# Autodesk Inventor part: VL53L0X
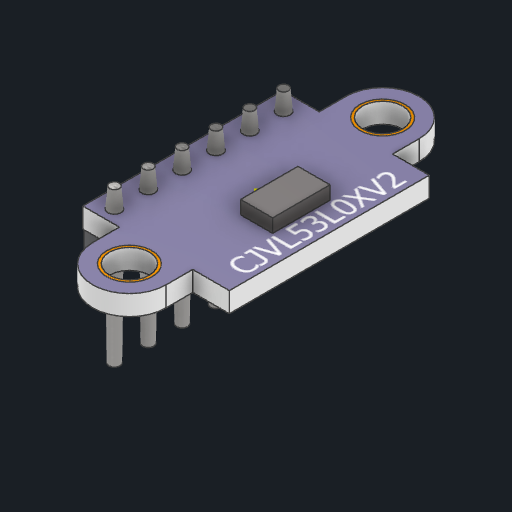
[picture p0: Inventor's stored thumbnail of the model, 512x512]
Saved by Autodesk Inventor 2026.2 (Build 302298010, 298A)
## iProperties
Created: 2026-04
Part Number: VL53L0X
Material: PPS 플라스틱
Document SubType Name: Modeling
Designer: work
Density: 1.637 g/cm^3
Appearance: 매끄러움 - 흰색
Author: work
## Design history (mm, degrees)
sketch "스케치1"
  geometry: L1 (-5.5, 7.5)-(5.5, 7.5); L2 (5.5, 7.5)-(5.5, -7.5); L3 (5.5, -7.5)-(-5.5, -7.5); L4 (-5.5, -7.5)-(-5.5, 7.5); L5 (-5.5, 7.5)-(5.5, -7.5); L6 (5.5, 7.5)-(-5.5, -7.5); L7 (0, 9.5)-(0, -9.5); L8 (0, 9.5)-(0, -9.5); L9 (-2.75, 9.5)-(-2.75, -9.5); L10 (2.75, -9.5)-(2.75, 9.5); C1 r 1.5 at (0, 9.5); C2 r 1.5 at (0, -9.5); A1 r 2.75 centre (0, 9.5) between (2.75, 9.5) and (-2.75, 9.5); A2 r 2.75 centre (0, -9.5) between (-2.75, -9.5) and (2.75, -9.5); 6 further points
  constraints: 22 end point, 6 midpoint, 4 centre point, 4 equal length, 4 point on circle, 4 tangent, 2 coincident, 1 horizontal, 1 perpendicular, 1 vertical
  dimensions: "d0" = 11 distance of L2.end L3.end; "d1" = 15 distance of L1.end L2.end; "d2" = 19 distance of L7.start L7.end; "d3" = 5.5 diameter of A2; "d4" = 3 diameter of C1; "d5" = 3 diameter of C2
extrude "돌출1" new body sketch "스케치1" distance "d6" = 1.5; taper "d7" = 0 deg
sketch "스케치2"
  geometry: L1 (5.5, -7.5)-(5.5, 7.5) reference; L2 (5.5, 0)-(-5.5, 0); L3 (-5.5, 7.5)-(-5.5, -7.5) reference; L4 (3.4, -2.15)-(1, -2.15); L5 (1, -2.15)-(1, 2.15); L6 (1, 2.15)-(3.4, 2.15); L7 (3.4, 2.15)-(3.4, -2.15); L8 (3.4, -2.15)-(1, 2.15); L9 (1, -2.15)-(3.4, 2.15); 2 further points
  constraints: 14 end point, 4 midpoint, 2 parallel, 1 horizontal, 1 perpendicular, 1 point on line
  dimensions: "d8" = 2.4 distance of L5.end L6.end; "d9" = 4.3 distance of L4.end L5.end; "d10" = 4.5 distance between parallel lines of L1 L5
extrude "돌출2" join sketch "스케치2" distance "d11" = 1; taper "d12" = 0 deg
sketch "스케치3"
  geometry: L1 (0, 0)-(-5.5, 0); L2 (-5.5, -7.5)-(-5.5, 7.5) reference; L3 (-3.1, 7.45)-(-5.5, 7.45); L4 (-5.5, 7.45)-(-5.5, -7.45); L5 (-5.5, -7.45)-(-3.1, -7.45); L6 (-3.1, -7.45)-(-3.1, 7.45); L7 (-3.1, 7.45)-(-5.5, -7.45); L8 (-5.5, 7.45)-(-3.1, -7.45); L9 (-5.45, -7.45)-(-5.45, 7.45); 2 further points
  constraints: 16 end point, 4 point on line, 3 midpoint, 2 parallel, 2 perpendicular, 1 horizontal
  dimensions: "d13" = 2.4 distance of L4.end L5.end; "d14" = 14.9 distance of L5.end L3.start; "d17" = 0.05 distance between parallel lines of L2 L9
extrude "돌출3" join sketch "스케치3" distance "d15" = 1.5; taper "d16" = 0 deg
sketch "스케치4"
  geometry: L1 (1, 2.15)-(3.4, 2.15) reference; L2 (3.4, 2.15)-(3.4, -2.15) reference; L3 (3.4, -2.15)-(1, -2.15) reference; L4 (1, -2.15)-(1, 2.15) reference; L5 (2.75, -9.5)-(2.75, -7.5) reference; L6 (2.75, -7.5)-(5.5, -7.5) reference; L7 (5.5, -7.5)-(5.5, 7.5) reference; L8 (5.5, 7.5)-(2.75, 7.5) reference; L9 (2.75, 7.5)-(2.75, 9.5) reference; L10 (-2.75, 9.5)-(-2.75, 7.5) reference; L11 (-2.75, 7.5)-(-5.5, 7.5) reference; L12 (-5.5, 7.5)-(-5.5, -7.5) reference; L13 (-5.5, -7.5)-(-2.75, -7.5) reference; L14 (-2.75, -7.5)-(-2.75, -9.5) reference; C1 r 1.5 at (0, 9.5) reference; C2 r 1.5 at (0, -9.5) reference; C3 r 1.7 at (0, 9.5); C4 r 1.7 at (0, -9.5); A1 r 2.75 centre (0, -9.5) between (-2.75, -9.5) and (2.75, -9.5) reference; A2 r 2.75 centre (0, 9.5) between (2.75, 9.5) and (-2.75, 9.5) reference; 1 further point
  constraints: 2 centre point, 2 coincident
  dimensions: "d18" = 0.2 radial gap between concentric circles of C3 C1; "d19" = 0.2 radial gap between concentric circles of C4 C2
feature "표식1" sketch "스케치4"
sketch "스케치5"
  geometry: L1 (-3.1, 2.05)-(-3.1, 16.95) reference; L2 (-5.5, 2)-(-2.75, 2) reference; L3 (-4.125, 2)-(-4.125, 17); L4 (-2.75, 17)-(-5.5, 17) reference; C1 r 0.5 at (-4.125, 3); C2 r 0.5 at (-4.125, 5.54); C3 r 0.5 at (-4.125, 8.08); C4 r 0.5 at (-4.125, 10.62); C5 r 0.5 at (-4.125, 13.16); C6 r 0.5 at (-4.125, 15.7); 1 further point
  constraints: 6 centre point, 2 end point, 2 midpoint, 1 point on line, 1 vertical, 10 other
  dimensions: "d20" = 1 distance from line of L2 C1.centre; "d23" = 2.54 distance of C1.centre C2.centre; "d28" = 1 diameter of C1
  node "스케치 - 직사각형 패턴1" dims "d23" = 2.54, "d26" = 10
extrude "돌출4" join sketch "스케치5" distance "d29" = 1.5; taper "d30" = -5 deg
extrude "돌출5" join sketch "스케치5" distance "d31" = 10; taper "d32" = -0.5 deg
sketch "스케치6" dims "d1" = 15
  geometry: L1 (3.571, 3.54)-(3.571, 15.852); L2 (3.571, 15.852)-(5.134, 15.852); L3 (5.134, 15.852)-(5.134, 3.54); L4 (5.134, 3.54)-(3.571, 3.54); 1 further point
  constraints: 2 other
node "솔리드1"
node "투영된 루프1"
